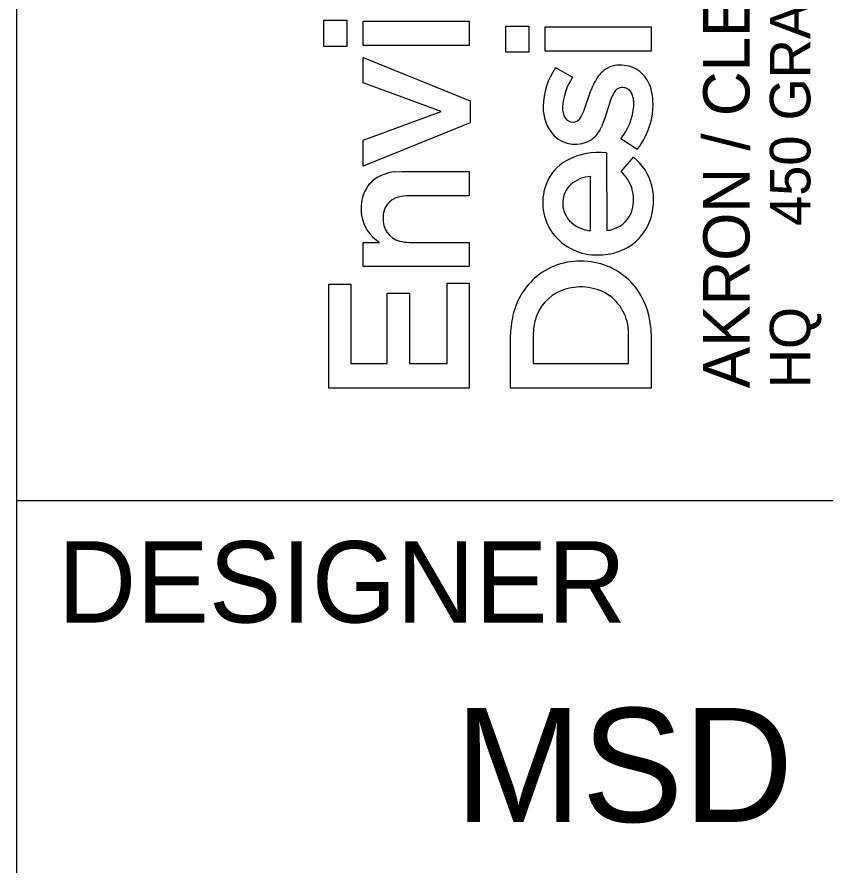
# Model space of a CAD drawing. Extents: x -6.7 to 34, y -1.6 to 22.
# Drawn here: x 32 to 32.993, y 2.552 to 3.594 of the extents above; entities that cross this region are included whole.
import ezdxf

# ---------------------------------------------------------------- set-up
doc = ezdxf.new("R2010")
doc.units = 0
doc.layers.add('SH_Border', color=7, linetype='Continuous')
doc.layers.add('SH_Cut_Line', color=7, linetype='Continuous')

msp = doc.modelspace()

# ---------------------------------------------------------------- linework, layer by layer
at = {"layer": 'SH_Border'}
for p, q in [((32, 0.5), (32, 21.5)), ((32, 3), (33.5, 3))]:
    msp.add_line(p, q, dxfattribs=at)
at = {"layer": 'SH_Cut_Line'}
for p, q in [((32.3771, 3.5582), (32.3771, 3.5903)), ((32.3771, 3.5903), (32.4054, 3.5903)), ((32.4054, 3.5903), (32.4054, 3.5582)), ((32.4254, 3.5594), (32.4254, 3.5893)), ((32.4254, 3.5893), (32.5557, 3.5893)), ((32.5557, 3.5893), (32.5557, 3.5594)), ((32.6005, 3.5511), (32.6005, 3.5832)), ((32.6005, 3.5832), (32.6289, 3.5832)), ((32.6289, 3.5832), (32.6289, 3.5511)), ((32.6489, 3.5523), (32.6489, 3.5822)), ((32.6489, 3.5822), (32.7792, 3.5822)), ((32.7792, 3.5822), (32.7792, 3.5523)), ((32.4054, 3.5582), (32.3771, 3.5582)), ((32.5557, 3.5594), (32.4254, 3.5594)), ((32.4254, 3.5133), (32.4254, 3.5446)), ((32.4254, 3.5446), (32.5567, 3.4913)), ((32.6289, 3.5511), (32.6005, 3.5511)), ((32.7792, 3.5523), (32.6489, 3.5523)), ((32.6615, 3.5321), (32.6827, 3.5203)), ((32.5212, 3.478), (32.4254, 3.5133)), ((32.7048, 3.5026), (32.7104, 3.5153)), ((32.6967, 3.4787), (32.7048, 3.5026)), ((32.7298, 3.4933), (32.7221, 3.4688)), ((32.7334, 3.501), (32.7298, 3.4933)), ((32.5567, 3.4913), (32.5567, 3.4644)), ((32.4254, 3.4429), (32.5212, 3.478)), ((32.693, 3.4712), (32.6967, 3.4787)), ((32.5567, 3.4644), (32.4254, 3.4109)), ((32.7221, 3.4688), (32.7182, 3.4592)), ((32.4254, 3.4109), (32.4254, 3.4429)), ((32.7621, 3.4314), (32.742, 3.4447)), ((32.7245, 3.4275), (32.7246, 3.3319)), ((32.7423, 3.4046), (32.7577, 3.422)), ((32.4644, 3.404), (32.4729, 3.4044)), ((32.4729, 3.4044), (32.5557, 3.4044)), ((32.5557, 3.4044), (32.5557, 3.3746)), ((32.7049, 3.3318), (32.7049, 3.3983)), ((32.5557, 3.3746), (32.4814, 3.3746)), ((32.7036, 3.3317), (32.7049, 3.3318)), ((32.4254, 3.2875), (32.4254, 3.3173)), ((32.4254, 3.3173), (32.4455, 3.3173)), ((32.4822, 3.3173), (32.5557, 3.3173)), ((32.5557, 3.3173), (32.5557, 3.2876)), ((32.5557, 3.2876), (32.4254, 3.2875)), ((32.383, 3.1379), (32.383, 3.266)), ((32.383, 3.266), (32.4101, 3.266)), ((32.4101, 3.266), (32.4101, 3.1683)), ((32.5286, 3.1683), (32.5286, 3.2672)), ((32.5286, 3.2672), (32.5557, 3.2672)), ((32.5557, 3.2672), (32.5557, 3.1379)), ((32.455, 3.1683), (32.455, 3.2549)), ((32.455, 3.2549), (32.4822, 3.2549)), ((32.4822, 3.2549), (32.4822, 3.1683)), ((32.6347, 3.2118), (32.6341, 3.2023)), ((32.7785, 3.215), (32.7792, 3.2021)), ((32.6064, 3.138), (32.6064, 3.204)), ((32.6341, 3.2023), (32.6341, 3.1684)), ((32.7515, 3.1683), (32.7515, 3.2024)), ((32.7792, 3.2021), (32.7792, 3.138)), ((32.4101, 3.1683), (32.455, 3.1683)), ((32.4822, 3.1683), (32.5286, 3.1683)), ((32.6341, 3.1684), (32.7515, 3.1683)), ((32.5557, 3.1379), (32.383, 3.1379)), ((32.7792, 3.138), (32.6064, 3.138))]:
    msp.add_line(p, q, dxfattribs=at)
for points in [[(32.3771, 3.5582), (32.3771, 3.5903), (32.4054, 3.5903), (32.4054, 3.5582)], [(32.4254, 3.5594), (32.4254, 3.5893), (32.5557, 3.5893), (32.5557, 3.5594)], [(32.6005, 3.5511), (32.6005, 3.5832), (32.6289, 3.5832), (32.6289, 3.5511)], [(32.6489, 3.5523), (32.6489, 3.5822), (32.7792, 3.5822), (32.7792, 3.5523)], [(32.4254, 3.4109), (32.4254, 3.4429), (32.5212, 3.478), (32.4254, 3.5133), (32.4254, 3.5446), (32.5567, 3.4913), (32.5567, 3.4644)], [(32.383, 3.1379), (32.383, 3.266), (32.4101, 3.266), (32.4101, 3.1683), (32.455, 3.1683), (32.455, 3.2549), (32.4822, 3.2549), (32.4822, 3.1683), (32.5286, 3.1683), (32.5286, 3.2672), (32.5557, 3.2672), (32.5557, 3.1379)]]:
    msp.add_lwpolyline(points, close=True, dxfattribs=at)
for points in [[(32.6615, 3.5321), (32.6827, 3.5203)], [(32.693, 3.4712), (32.6967, 3.4787), (32.7048, 3.5026), (32.7104, 3.5153)], [(32.7334, 3.501), (32.7298, 3.4933), (32.7221, 3.4688), (32.7182, 3.4592)], [(32.7621, 3.4314), (32.742, 3.4447)], [(32.7245, 3.4275), (32.7246, 3.3319)], [(32.7423, 3.4046), (32.7577, 3.422)], [(32.4644, 3.404), (32.4729, 3.4044), (32.5557, 3.4044), (32.5557, 3.3746), (32.4814, 3.3746)], [(32.7036, 3.3317), (32.7049, 3.3318), (32.7049, 3.3983)], [(32.4254, 3.2875), (32.4254, 3.3173), (32.4455, 3.3173)], [(32.4822, 3.3173), (32.5557, 3.3173), (32.5557, 3.2876), (32.4254, 3.2875)], [(32.7785, 3.215), (32.7792, 3.2021), (32.7792, 3.138), (32.6064, 3.138)], [(32.6347, 3.2118), (32.6341, 3.2023), (32.6341, 3.1684), (32.7515, 3.1683), (32.7515, 3.2024)], [(32.6064, 3.138), (32.6064, 3.204)]]:
    msp.add_lwpolyline(points, dxfattribs=at)
for centre, radius, start, end in [((32.7406, 3.5026), 0.0326, 80.1719, 122.5197), ((32.7406, 3.5026), 0.0326, 80.1719, 122.5197), ((32.7428, 3.4982), 0.0367, 47.7934, 84.6892), ((32.7428, 3.4982), 0.0367, 47.7934, 84.6892), ((32.7364, 3.4826), 0.0897, 146.531, 178.7571), ((32.7364, 3.4826), 0.0897, 146.531, 178.7571), ((32.7466, 3.4971), 0.0405, 125.5118, 153.4159), ((32.7466, 3.4971), 0.0405, 125.5118, 153.4159), ((32.7379, 3.4946), 0.0427, 14.9966, 46.2063), ((32.7379, 3.4946), 0.0427, 14.9966, 46.2063), ((32.7452, 3.4789), 0.0749, 146.5112, 176.9101), ((32.7452, 3.4789), 0.0749, 146.5112, 176.9101), ((32.7438, 3.4963), 0.0114, 76.6609, 155.7053), ((32.7438, 3.4963), 0.0114, 76.6609, 155.7053), ((32.744, 3.4951), 0.0126, 21.5098, 78.5262), ((32.744, 3.4951), 0.0126, 21.5098, 78.5262), ((32.7104, 3.4867), 0.0712, 355.8306, 15.3914), ((32.7104, 3.4867), 0.0712, 355.8306, 15.3914), ((32.7259, 3.4877), 0.0321, 354.5726, 22.068), ((32.7259, 3.4877), 0.0321, 354.5726, 22.068), ((32.6967, 3.4824), 0.0501, 177.5366, 222.7932), ((32.6967, 3.4824), 0.0501, 177.5366, 222.7932), ((32.6931, 3.4823), 0.0228, 178.4747, 211.0868), ((32.6931, 3.4823), 0.0228, 178.4747, 211.0868), ((32.6825, 3.4915), 0.0757, 321.811, 354.7969), ((32.6825, 3.4915), 0.0757, 321.811, 354.7969), ((32.6834, 3.4759), 0.0107, 267.716, 333.7337), ((32.6834, 3.4759), 0.0107, 267.716, 333.7337), ((32.6895, 3.4882), 0.0922, 321.9777, 355.8738), ((32.6895, 3.4882), 0.0922, 321.9777, 355.8738), ((32.6833, 3.4767), 0.0115, 212.2368, 268.3777), ((32.6833, 3.4767), 0.0115, 212.2368, 268.3777), ((32.681, 3.4758), 0.0408, 308.0877, 335.9874), ((32.681, 3.4758), 0.0408, 308.0877, 335.9874), ((32.686, 3.4753), 0.0375, 225.9854, 302.4797), ((32.686, 3.4753), 0.0375, 225.9854, 302.4797), ((32.7152, 3.3441), 0.0838, 83.615, 118.2876), ((32.7152, 3.3441), 0.0838, 83.615, 118.2876), ((32.7174, 3.3717), 0.0644, 13.5336, 51.3615), ((32.7174, 3.3717), 0.0644, 13.5336, 51.3615), ((32.7024, 3.3691), 0.0558, 118.8308, 160.6244), ((32.7024, 3.3691), 0.0558, 118.8308, 160.6244), ((32.4687, 3.3543), 0.0499, 94.9696, 130.2225), ((32.4687, 3.3543), 0.0499, 94.9696, 130.2225), ((32.7079, 3.3561), 0.0424, 94.008, 130.8817), ((32.7079, 3.3561), 0.0424, 94.008, 130.8817), ((32.7038, 3.3656), 0.0549, 19.0357, 45.4406), ((32.7038, 3.3656), 0.0549, 19.0357, 45.4406), ((32.4635, 3.3626), 0.0402, 132.2219, 161.6818), ((32.4635, 3.3626), 0.0402, 132.2219, 161.6818), ((32.7005, 3.3663), 0.0298, 132.9851, 177.179), ((32.7005, 3.3663), 0.0298, 132.9851, 177.179), ((32.7104, 3.3661), 0.0644, 160.5201, 215.7831), ((32.7104, 3.3661), 0.0644, 160.5201, 215.7831), ((32.7107, 3.3697), 0.047, 344.6059, 17.007), ((32.7107, 3.3697), 0.047, 344.6059, 17.007), ((32.7064, 3.3692), 0.0758, 339.3542, 13.3785), ((32.7064, 3.3692), 0.0758, 339.3542, 13.3785), ((32.4787, 3.3582), 0.056, 162.2736, 187.7919), ((32.4787, 3.3582), 0.056, 162.2736, 187.7919), ((32.4748, 3.3487), 0.025, 103.6865, 182.2187), ((32.4748, 3.3487), 0.025, 103.6865, 182.2187), ((32.4811, 3.3286), 0.046, 89.6049, 105.3284), ((32.4811, 3.3286), 0.046, 89.6049, 105.3284), ((32.7017, 3.365), 0.0311, 175.0013, 223.283), ((32.7017, 3.365), 0.0311, 175.0013, 223.283), ((32.7224, 3.3671), 0.035, 288.0077, 343.5508), ((32.7224, 3.3671), 0.035, 288.0077, 343.5508), ((32.4703, 3.358), 0.0476, 188.962, 238.7037), ((32.4703, 3.358), 0.0476, 188.962, 238.7037), ((32.4773, 3.3456), 0.0276, 175.5854, 255.1439), ((32.4773, 3.3456), 0.0276, 175.5854, 255.1439), ((32.7089, 3.3736), 0.0423, 225.0619, 262.7974), ((32.7089, 3.3736), 0.0423, 225.0619, 262.7974), ((32.7189, 3.3652), 0.0626, 300.9427, 338.7323), ((32.7189, 3.3652), 0.0626, 300.9427, 338.7323), ((32.7125, 3.3705), 0.0687, 217.7452, 271.6543), ((32.7125, 3.3705), 0.0687, 217.7452, 271.6543), ((32.7247, 3.3522), 0.0202, 269.7003, 294.8711), ((32.7247, 3.3522), 0.0202, 269.7003, 294.8711), ((32.4818, 3.3595), 0.0422, 254.0916, 270.5284), ((32.4818, 3.3595), 0.0422, 254.0916, 270.5284), ((32.7155, 3.3724), 0.0706, 269.2048, 300.3341), ((32.7155, 3.3724), 0.0706, 269.2048, 300.3341), ((32.6923, 3.2079), 0.0864, 81.194, 125.9984), ((32.6923, 3.2079), 0.0864, 81.194, 125.9984), ((32.6946, 3.2113), 0.0827, 37.8521, 82.402), ((32.6946, 3.2113), 0.0827, 37.8521, 82.402), ((32.6939, 3.2089), 0.0865, 127.2362, 165.148), ((32.6939, 3.2089), 0.0865, 127.2362, 165.148), ((32.6889, 3.2078), 0.054, 106.1881, 157.3861), ((32.6889, 3.2078), 0.054, 106.1881, 157.3861), ((32.6928, 3.1986), 0.0639, 55.6727, 107.2093), ((32.6928, 3.1986), 0.0639, 55.6727, 107.2093), ((32.6859, 3.2057), 0.0931, 5.7333, 37.304), ((32.6859, 3.2057), 0.0931, 5.7333, 37.304), ((32.6929, 3.205), 0.0587, 357.4662, 52.2665), ((32.6929, 3.205), 0.0587, 357.4662, 52.2665), ((32.7143, 3.2028), 0.1078, 164.7861, 179.3704), ((32.7143, 3.2028), 0.1078, 164.7861, 179.3704), ((32.6983, 3.2039), 0.0641, 157.3571, 172.9275), ((32.6983, 3.2039), 0.0641, 157.3571, 172.9275)]:
    msp.add_arc(centre, radius, start, end, dxfattribs=at)

# ---------------------------------------------------------------- texts
for s, height, p in [('450 GRANT ST., AKRON, OH  44311', 0.049846, (32.9749, 3.3374)), ('AKRON / CLEVELAND / COLUMBUS', 0.056969, (32.9001, 3.138)), ('HQ ', 0.04985, (32.9749, 3.138))]:
    msp.add_text(s, height=height, rotation=90, dxfattribs=at).set_placement(p)
for s, height, p in [('DESIGNER', 0.1, (32.05, 2.85)), ('MSD', 0.14, (32.5379, 2.605))]:
    msp.add_text(s, height=height, dxfattribs=at).set_placement(p)

doc.saveas('drawing.dxf')
